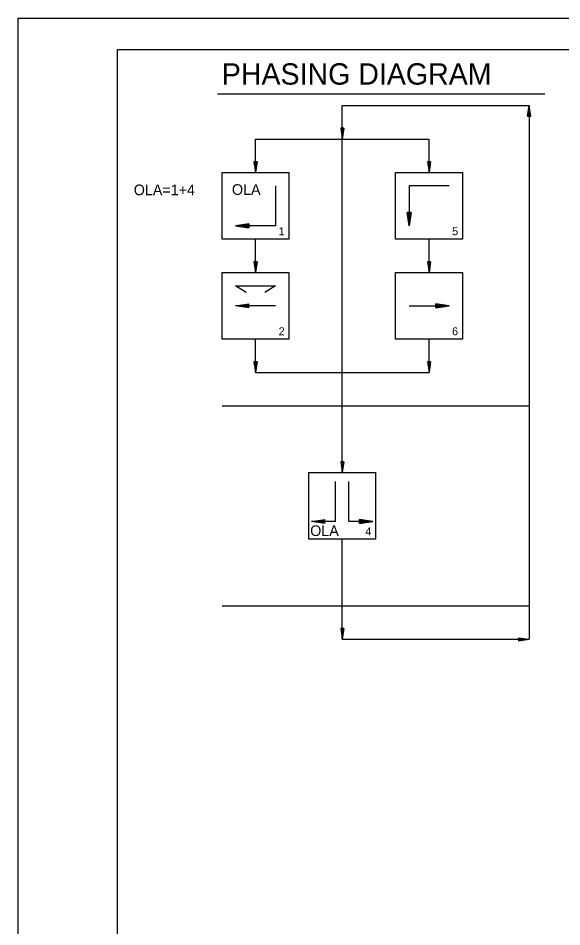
# Model space of a CAD drawing. Extents: x 660063 to 664816, y 641756 to 643817.
# Drawn here: x 661410.8 to 661614.4, y 642548.1 to 642888.7 of the extents above; entities that cross this region are included whole.
import ezdxf

# ---------------------------------------------------------------- set-up
doc = ezdxf.new("R2010")
doc.units = 0
for name, color, linetype in [('Default', 7, 'Continuous'), ('R_Border', 7, 'Continuous'), ('R_Draft', 7, 'Continuous'), ('R_No Plot', 7, 'Continuous'), ('T_Drafting', 7, 'Continuous')]:
    doc.layers.add(name, color=color, linetype=linetype)

msp = doc.modelspace()

# ---------------------------------------------------------------- linework, layer by layer
at = {"layer": 'Default'}
for p, q in [((661485.44, 642860.27), (661608.09, 642860.27)), ((661601.57, 642851.87), (661602.17, 642855.87)), ((661602.77, 642851.87), (661602.17, 642855.87)), ((661601.67, 642851.87), (661602.17, 642855.2)), ((661601.77, 642851.87), (661602.17, 642854.51)), ((661601.87, 642851.87), (661602.17, 642853.85)), ((661601.97, 642851.87), (661602.17, 642853.17)), ((661602.07, 642851.87), (661602.17, 642852.5)), ((661602.67, 642851.87), (661602.17, 642855.2)), ((661602.56, 642851.87), (661602.17, 642854.51)), ((661602.46, 642851.87), (661602.17, 642853.85)), ((661602.36, 642851.87), (661602.17, 642853.17)), ((661602.26, 642851.87), (661602.17, 642852.5)), ((661601.57, 642851.87), (661602.77, 642851.87)), ((661531.57, 642847.37), (661532.17, 642843.37)), ((661532.77, 642847.37), (661531.57, 642847.37)), ((661531.67, 642847.37), (661532.17, 642844.04)), ((661531.77, 642847.37), (661532.17, 642844.72)), ((661531.87, 642847.37), (661532.17, 642845.39)), ((661531.97, 642847.37), (661532.17, 642846.07)), ((661532.07, 642847.37), (661532.17, 642846.74)), ((661532.77, 642847.37), (661532.17, 642843.37)), ((661532.36, 642847.37), (661532.17, 642846.07)), ((661532.56, 642847.37), (661532.17, 642844.72)), ((661532.67, 642847.37), (661532.17, 642844.04)), ((661532.46, 642847.37), (661532.17, 642845.39)), ((661532.26, 642847.37), (661532.17, 642846.74)), ((661499.07, 642834.87), (661499.67, 642830.87)), ((661500.27, 642834.87), (661499.07, 642834.87)), ((661499.17, 642834.87), (661499.67, 642831.54)), ((661499.27, 642834.87), (661499.67, 642832.22)), ((661499.37, 642834.87), (661499.67, 642832.89)), ((661499.47, 642834.87), (661499.67, 642833.57)), ((661499.57, 642834.87), (661499.67, 642834.24)), ((661500.27, 642834.87), (661499.67, 642830.87)), ((661499.86, 642834.87), (661499.67, 642833.57)), ((661500.06, 642834.87), (661499.67, 642832.22)), ((661500.17, 642834.87), (661499.67, 642831.54)), ((661499.96, 642834.87), (661499.67, 642832.89)), ((661499.76, 642834.87), (661499.67, 642834.24)), ((661564.07, 642834.87), (661564.67, 642830.87)), ((661565.27, 642834.87), (661564.07, 642834.87)), ((661564.17, 642834.87), (661564.67, 642831.54)), ((661564.27, 642834.87), (661564.67, 642832.22)), ((661564.37, 642834.87), (661564.67, 642832.89)), ((661564.47, 642834.87), (661564.67, 642833.57)), ((661564.57, 642834.87), (661564.67, 642834.24)), ((661565.27, 642834.87), (661564.67, 642830.87)), ((661564.86, 642834.87), (661564.67, 642833.57)), ((661565.06, 642834.87), (661564.67, 642832.22)), ((661565.17, 642834.87), (661564.67, 642831.54)), ((661564.96, 642834.87), (661564.67, 642832.89)), ((661564.76, 642834.87), (661564.67, 642834.24)), ((661499.07, 642797.37), (661499.67, 642793.37)), ((661500.27, 642797.37), (661499.07, 642797.37)), ((661499.17, 642797.37), (661499.67, 642794.04)), ((661499.27, 642797.37), (661499.67, 642794.72)), ((661499.37, 642797.37), (661499.67, 642795.39)), ((661499.47, 642797.37), (661499.67, 642796.07)), ((661499.57, 642797.37), (661499.67, 642796.74)), ((661500.27, 642797.37), (661499.67, 642793.37)), ((661499.86, 642797.37), (661499.67, 642796.07)), ((661500.06, 642797.37), (661499.67, 642794.72)), ((661500.17, 642797.37), (661499.67, 642794.04)), ((661499.96, 642797.37), (661499.67, 642795.39)), ((661499.76, 642797.37), (661499.67, 642796.74)), ((661564.07, 642797.37), (661564.67, 642793.37)), ((661565.27, 642797.37), (661564.07, 642797.37)), ((661564.17, 642797.37), (661564.67, 642794.04)), ((661564.27, 642797.37), (661564.67, 642794.72)), ((661564.37, 642797.37), (661564.67, 642795.39)), ((661564.47, 642797.37), (661564.67, 642796.07)), ((661564.57, 642797.37), (661564.67, 642796.74)), ((661565.27, 642797.37), (661564.67, 642793.37)), ((661564.86, 642797.37), (661564.67, 642796.07)), ((661565.06, 642797.37), (661564.67, 642794.72)), ((661565.17, 642797.37), (661564.67, 642794.04)), ((661564.96, 642797.37), (661564.67, 642795.39)), ((661564.76, 642797.37), (661564.67, 642796.74)), ((661499.07, 642759.87), (661499.67, 642755.87)), ((661500.27, 642759.87), (661499.07, 642759.87)), ((661499.17, 642759.87), (661499.67, 642756.54)), ((661499.27, 642759.87), (661499.67, 642757.22)), ((661499.37, 642759.87), (661499.67, 642757.89)), ((661499.47, 642759.87), (661499.67, 642758.57)), ((661499.57, 642759.87), (661499.67, 642759.24)), ((661500.27, 642759.87), (661499.67, 642755.87)), ((661499.86, 642759.87), (661499.67, 642758.57)), ((661500.06, 642759.87), (661499.67, 642757.22)), ((661500.17, 642759.87), (661499.67, 642756.54)), ((661499.96, 642759.87), (661499.67, 642757.89)), ((661499.76, 642759.87), (661499.67, 642759.24)), ((661564.07, 642759.87), (661564.67, 642755.87)), ((661565.27, 642759.87), (661564.07, 642759.87)), ((661564.17, 642759.87), (661564.67, 642756.54)), ((661564.27, 642759.87), (661564.67, 642757.22)), ((661564.37, 642759.87), (661564.67, 642757.89)), ((661564.47, 642759.87), (661564.67, 642758.57)), ((661564.57, 642759.87), (661564.67, 642759.24)), ((661565.27, 642759.87), (661564.67, 642755.87)), ((661564.86, 642759.87), (661564.67, 642758.57)), ((661565.06, 642759.87), (661564.67, 642757.22)), ((661565.17, 642759.87), (661564.67, 642756.54)), ((661564.96, 642759.87), (661564.67, 642757.89)), ((661564.76, 642759.87), (661564.67, 642759.24)), ((661531.57, 642722.37), (661532.17, 642718.37)), ((661532.77, 642722.37), (661531.57, 642722.37)), ((661531.67, 642722.37), (661532.17, 642719.04)), ((661531.77, 642722.37), (661532.17, 642719.72)), ((661531.87, 642722.37), (661532.17, 642720.39)), ((661531.97, 642722.37), (661532.17, 642721.07)), ((661532.07, 642722.37), (661532.17, 642721.74)), ((661532.77, 642722.37), (661532.17, 642718.37)), ((661532.36, 642722.37), (661532.17, 642721.07)), ((661532.56, 642722.37), (661532.17, 642719.72)), ((661532.67, 642722.37), (661532.17, 642719.04)), ((661532.46, 642722.37), (661532.17, 642720.39)), ((661532.26, 642722.37), (661532.17, 642721.74)), ((661531.57, 642659.87), (661532.17, 642655.87)), ((661532.77, 642659.87), (661531.57, 642659.87)), ((661531.67, 642659.87), (661532.17, 642656.54)), ((661531.77, 642659.87), (661532.17, 642657.22)), ((661531.87, 642659.87), (661532.17, 642657.89)), ((661531.97, 642659.87), (661532.17, 642658.57)), ((661532.07, 642659.87), (661532.17, 642659.24)), ((661532.77, 642659.87), (661532.17, 642655.87)), ((661532.36, 642659.87), (661532.17, 642658.57)), ((661532.56, 642659.87), (661532.17, 642657.22)), ((661532.67, 642659.87), (661532.17, 642656.54)), ((661532.46, 642659.87), (661532.17, 642657.89)), ((661532.26, 642659.87), (661532.17, 642659.24))]:
    msp.add_line(p, q, dxfattribs=at)
at = {"layer": 'R_Border'}
for p, q in [((661447.99, 642876.97), (662396.53, 642876.97)), ((661447.99, 642260.59), (661447.99, 642876.97))]:
    msp.add_line(p, q, dxfattribs=at)
at = {"layer": 'R_Draft'}
for p, q in [((661598.17, 642656.47), (661602.17, 642655.87)), ((661598.17, 642656.47), (661598.17, 642655.27)), ((661598.17, 642656.37), (661601.5, 642655.87)), ((661598.17, 642656.27), (661600.81, 642655.87)), ((661598.17, 642656.17), (661600.14, 642655.87)), ((661598.17, 642656.06), (661599.47, 642655.87)), ((661598.17, 642655.96), (661598.8, 642655.87)), ((661598.17, 642655.27), (661602.17, 642655.87)), ((661598.17, 642655.67), (661599.47, 642655.87)), ((661598.17, 642655.47), (661600.81, 642655.87)), ((661598.17, 642655.37), (661601.5, 642655.87)), ((661598.17, 642655.57), (661600.14, 642655.87)), ((661598.17, 642655.77), (661598.8, 642655.87))]:
    msp.add_line(p, q, dxfattribs=at)
at = {"layer": 'R_No Plot'}
msp.add_line((661410.79, 642888.66), (662410.79, 642888.66), dxfattribs=at)
msp.add_lwpolyline([(661410.77, 642888.66), (662410.79, 642888.66), (662410.79, 642248.64), (661410.77, 642248.64)], close=True, dxfattribs=at)
at = {"layer": 'T_Drafting'}
for p, q in [((661532.17, 642855.87), (661602.17, 642855.87)), ((661532.17, 642718.37), (661532.17, 642855.87)), ((661602.17, 642855.87), (661602.17, 642655.87)), ((661499.67, 642830.87), (661499.67, 642843.37)), ((661499.67, 642843.37), (661564.67, 642843.37)), ((661564.67, 642830.87), (661564.67, 642843.37)), ((661507.17, 642825.87), (661507.17, 642810.87)), ((661572.17, 642825.87), (661557.17, 642825.87)), ((661557.17, 642825.87), (661557.17, 642810.87)), ((661557.17, 642810.87), (661556.42, 642815.87)), ((661557.92, 642815.87), (661556.42, 642815.87)), ((661556.54, 642815.87), (661557.17, 642811.7)), ((661557.17, 642812.56), (661556.67, 642815.87)), ((661556.79, 642815.87), (661557.17, 642813.4)), ((661557.17, 642814.24), (661556.92, 642815.87)), ((661557.05, 642815.87), (661557.17, 642815.08)), ((661557.17, 642815.08), (661557.28, 642815.87)), ((661557.41, 642815.87), (661557.17, 642814.24)), ((661557.17, 642813.4), (661557.54, 642815.87)), ((661557.66, 642815.87), (661557.17, 642812.56)), ((661557.17, 642811.7), (661557.79, 642815.87)), ((661557.92, 642815.87), (661557.17, 642810.87)), ((661497.17, 642811.62), (661492.17, 642810.87)), ((661493, 642810.87), (661497.17, 642811.49)), ((661497.17, 642811.37), (661493.86, 642810.87)), ((661494.69, 642810.87), (661497.17, 642811.24)), ((661497.17, 642811.62), (661497.17, 642810.12)), ((661507.17, 642810.87), (661492.17, 642810.87)), ((661492.17, 642810.87), (661497.17, 642810.12)), ((661497.17, 642810.24), (661493, 642810.87)), ((661493.86, 642810.87), (661497.17, 642810.37)), ((661497.17, 642810.5), (661494.69, 642810.87)), ((661497.17, 642811.11), (661495.54, 642810.87)), ((661495.54, 642810.87), (661497.17, 642810.62)), ((661496.38, 642810.87), (661497.17, 642810.99)), ((661497.17, 642810.75), (661496.38, 642810.87)), ((661499.67, 642793.37), (661499.67, 642805.87)), ((661564.67, 642793.37), (661564.67, 642805.87)), ((661492.17, 642780.87), (661497.17, 642781.62)), ((661507.17, 642780.87), (661492.17, 642780.87)), ((661497.17, 642780.12), (661492.17, 642780.87)), ((661497.17, 642781.49), (661493, 642780.87)), ((661493, 642780.87), (661497.17, 642780.24)), ((661493.86, 642780.87), (661497.17, 642781.37)), ((661497.17, 642780.37), (661493.86, 642780.87)), ((661497.17, 642781.24), (661494.69, 642780.87)), ((661494.69, 642780.87), (661497.17, 642780.5)), ((661495.54, 642780.87), (661497.17, 642781.11)), ((661497.17, 642780.63), (661495.54, 642780.87)), ((661497.17, 642780.99), (661496.38, 642780.87)), ((661496.38, 642780.87), (661497.17, 642780.75)), ((661497.17, 642780.12), (661497.17, 642781.62)), ((661557.17, 642780.87), (661572.17, 642780.87)), ((661572.17, 642780.87), (661567.17, 642781.62)), ((661567.17, 642780.12), (661567.17, 642781.62)), ((661567.17, 642781.49), (661571.33, 642780.87)), ((661570.47, 642780.87), (661567.17, 642781.37)), ((661567.17, 642781.24), (661569.64, 642780.87)), ((661568.79, 642780.87), (661567.17, 642781.11)), ((661567.17, 642780.99), (661567.96, 642780.87)), ((661567.96, 642780.87), (661567.17, 642780.75)), ((661567.17, 642780.63), (661568.79, 642780.87)), ((661569.64, 642780.87), (661567.17, 642780.5)), ((661567.17, 642780.37), (661570.47, 642780.87)), ((661571.33, 642780.87), (661567.17, 642780.24)), ((661567.17, 642780.12), (661572.17, 642780.87)), ((661499.67, 642755.87), (661499.67, 642768.37)), ((661564.67, 642755.87), (661564.67, 642768.37)), ((661499.67, 642755.87), (661564.67, 642755.87)), ((661487.17, 642743.37), (661602.17, 642743.37)), ((661529.67, 642700.04), (661529.67, 642715.04)), ((661534.67, 642700.04), (661534.67, 642715.04)), ((661520.67, 642700.04), (661525.67, 642700.79)), ((661529.67, 642700.04), (661520.67, 642700.04)), ((661525.67, 642699.29), (661520.67, 642700.04)), ((661525.67, 642700.66), (661521.5, 642700.04)), ((661521.5, 642700.04), (661525.67, 642699.41)), ((661522.36, 642700.04), (661525.67, 642700.54)), ((661525.67, 642699.54), (661522.36, 642700.04)), ((661525.67, 642700.41), (661523.19, 642700.04)), ((661523.19, 642700.04), (661525.67, 642699.67)), ((661524.04, 642700.04), (661525.67, 642700.28)), ((661525.67, 642699.8), (661524.04, 642700.04)), ((661525.67, 642700.16), (661524.88, 642700.04)), ((661524.88, 642700.04), (661525.67, 642699.92)), ((661525.67, 642699.29), (661525.67, 642700.79)), ((661543.67, 642700.04), (661534.67, 642700.04)), ((661543.67, 642700.04), (661538.67, 642700.79)), ((661538.67, 642699.29), (661538.67, 642700.79)), ((661538.67, 642700.66), (661542.83, 642700.04)), ((661541.97, 642700.04), (661538.67, 642700.54)), ((661538.67, 642700.41), (661541.14, 642700.04)), ((661540.29, 642700.04), (661538.67, 642700.28)), ((661538.67, 642700.16), (661539.46, 642700.04)), ((661539.46, 642700.04), (661538.67, 642699.92)), ((661538.67, 642699.8), (661540.29, 642700.04)), ((661541.14, 642700.04), (661538.67, 642699.67)), ((661538.67, 642699.54), (661541.97, 642700.04)), ((661542.83, 642700.04), (661538.67, 642699.41)), ((661538.67, 642699.29), (661543.67, 642700.04)), ((661532.17, 642655.87), (661532.17, 642693.37)), ((661487.17, 642668.37), (661602.17, 642668.37)), ((661532.17, 642655.87), (661602.17, 642655.87))]:
    msp.add_line(p, q, dxfattribs=at)
for points in [[(661487.17, 642830.87), (661512.17, 642830.87), (661512.17, 642805.87), (661487.17, 642805.87)], [(661552.17, 642830.87), (661577.17, 642830.87), (661577.17, 642805.87), (661552.17, 642805.87)], [(661487.17, 642793.37), (661512.17, 642793.37), (661512.17, 642768.37), (661487.17, 642768.37)], [(661552.17, 642793.37), (661577.17, 642793.37), (661577.17, 642768.37), (661552.17, 642768.37)], [(661519.67, 642718.37), (661544.67, 642718.37), (661544.67, 642693.37), (661519.67, 642693.37)]]:
    msp.add_lwpolyline(points, close=True, dxfattribs=at)
msp.add_lwpolyline([(661496.17, 642785.87), (661492.17, 642788.37), (661507.17, 642788.37), (661503.17, 642785.87)], dxfattribs=at)

# ---------------------------------------------------------------- texts
at = {"layer": 'Default'}
for s, height, p in [('PHASING DIAGRAM', 8, (661487.04, 642863.74)), ('1', 3, (661508.32, 642807.29)), ('5', 3, (661573.32, 642807.29)), ('2', 3, (661508.32, 642769.79)), ('6', 3, (661573.32, 642769.79)), ('4', 3, (661540.82, 642694.79))]:
    msp.add_text(s, height=height, dxfattribs=at).set_placement(p)
at = {"layer": 'T_Drafting'}
for s, p in [('OLA=1+4', (661454.07, 642822.3)), ('OLA', (661490.85, 642822.42)), ('OLA', (661520.15, 642694.57))]:
    msp.add_text(s, height=4, dxfattribs=at).set_placement(p)

doc.saveas('drawing.dxf')
